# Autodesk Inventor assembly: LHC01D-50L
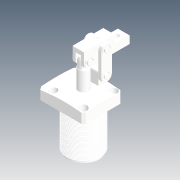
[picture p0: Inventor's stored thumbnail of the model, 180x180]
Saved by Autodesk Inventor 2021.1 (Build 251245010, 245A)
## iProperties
Created: 2019-04
Part Number: LHC01D-50L
Description: STEP AP214
Document SubType Name: Assembly
Designer: user
Title: LHC01D-50L.STEP
Revision Number: ÈÎºÎ
Sending System: SolidWorks 2016
Preprocessor: SwSTEP 2.0
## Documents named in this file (12)
- D:\Vault_2016\Projekty\Clamptek\Hydraulic\LHC01D\Inventor\LHC01D-50L\LHC01D-50L.iam
- D:\Vault_2016\Projekty\Clamptek\Hydraulic\LHC01D\Inventor\LHC01D-50L\LHC01D-50L(BT).ipt
- D:\Vault_2016\Projekty\Clamptek\Hydraulic\LHC01D\Inventor\LHC01D-50L\CPLCU-50-01_1.ipt
- D:\Vault_2016\Projekty\Clamptek\Hydraulic\LHC01D\Inventor\LHC01D-50L\CPLCU-50-02_1.ipt
- D:\Vault_2016\Projekty\Clamptek\Hydraulic\LHC01D\Inventor\LHC01D-50L\CPLCU-50-03_1.ipt
- D:\Vault_2016\Projekty\Clamptek\Hydraulic\LHC01D\Inventor\LHC01D-50L\CPLCU-50-04_1.ipt
- D:\Vault_2016\Projekty\Clamptek\Hydraulic\LHC01D\Inventor\LHC01D-50L\CPLCU-50-05_1.ipt
- D:\Vault_2016\Projekty\Clamptek\Hydraulic\LHC01D\Inventor\LHC01D-50L\CPLCU-50-07_1.ipt
- D:\Vault_2016\Projekty\Clamptek\Hydraulic\LHC01D\Inventor\LHC01D-50L\CPLCU-50-08_1.ipt
- D:\Vault_2016\Projekty\Clamptek\Hydraulic\LHC01D\Inventor\LHC01D-50L\M4ningjin_6.ipt
- D:\Vault_2016\Projekty\Clamptek\Hydraulic\LHC01D\Inventor\LHC01D-50L\¶ÂÍ·_11.ipt
- D:\Vault_2016\Projekty\Clamptek\Hydraulic\LHC01D\Inventor\LHC01D-50L\LHC01D050»îÈû¸Ë.ipt
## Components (24 placed, 24 different names)
1. LHC01D-50L(BT)_1
2. CPLCU-50-01_1_2
3. CPLCU-50-02_1_3
4. CPLCU-50-03_1_4
5. CPLCU-50-04_1_5
6. CPLCU-50-05_1_6
7. CPLCU-50-07_1_7
8. CPLCU-50-08_1_8
9. CPLCU-50-02_1_9
10. CPLCU-50-04_1_10
11. CPLCU-50-07_1_11
12. CPLCU-50-07_1_12
13. CPLCU-50-07_1_13
14. CPLCU-50-07_1_14
15. CPLCU-50-07_1_15
16. CPLCU-50-08_1_16
17. CPLCU-50-08_1_17
18. CPLCU-50-08_1_18
19. CPLCU-50-08_1_19
20. CPLCU-50-08_1_20
21. M4ningjin_6_21
22. ¶ÂÍ·_11_22
23. ¶ÂÍ·_11_23
24. LHC01D050»îÈû¸Ë_24
